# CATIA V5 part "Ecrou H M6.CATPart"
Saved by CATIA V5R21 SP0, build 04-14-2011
Part number: Ecrou H M6
Material "Acier": density 7860 kg/m3, Young's modulus 2e+11 Pa, Poisson ratio 0.266, thermal expansion 1.17e-05 1/K
Bounding box of the stored display mesh (mm): x -4 to 4, y -4.619 to 4.619, z 0 to 3
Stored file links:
  C:\Users\Olivier\Desktop\redaction CATIA (local)\CATIA\DONNEES\Exercice assemblage 1 (chassis et socle)\Assemblage chassis et socle (Product inclus)\Ecrou H M6.CATPart
  C:\Program Files\Dassault Systemes\B21\win_b64\startup\materials\French\Catalog.CATMaterial
  C:\Users\Olivier\Desktop\redaction CATIA (local)\CATIA\DONNEES\Exercice assemblage 1 (chassis et socle)\Assemblage chassis et socle (Product inclus)\CATIA_EnvironmentMap_Satin_512x512.jpg
  C:\Users\Olivier\Desktop\redaction CATIA (local)\pompe à moteur de ventilation refait\Pompe_a_moteur_de_ventilation.CATProduct
  C:\Users\Olivier\Desktop\redaction CATIA (local)\pompe à moteur de ventilation refait\Ecrou a collerette M5.CATPart
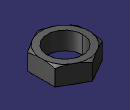
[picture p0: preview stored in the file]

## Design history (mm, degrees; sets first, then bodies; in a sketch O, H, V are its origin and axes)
Body1 (main body), material "Acier"
  Sketch1 on xy-plane, origin (0, 0, 0), H (1, 0, 0), V (0, 1, 0)
    circle A1 centre (0, 0) radius 3
    point P1 (4, -2.3094)
    point P2 (4, 2.3094)
    point P3 (0, 4.6188)
    point P4 (-4, 2.3094)
    point P5 (-4, -2.3094)
    point P6 (0, -4.6188)
    point P7 (4, 0)
    line L1 (4, -2.3094) -> (4, 2.3094)
    line L2 (4, 2.3094) -> (0, 4.6188)
    line L3 (0, 4.6188) -> (-4, 2.3094)
    line L4 (-4, 2.3094) -> (-4, -2.3094)
    line L5 (-4, -2.3094) -> (0, -4.6188)
    line L6 (0, -4.6188) -> (4, -2.3094)
    construction line L7 (0, 0) -> (4, 0)
    construction circle A2 centre (0, 0) radius 4.6188
    construction arc A3 centre (-4, -2.3094) radius 4.6188 from (-4, 2.3094) to (0, -4.6188) cw
    construction arc A4 centre (4, 2.3094) radius 4.6188 from (0, 4.6188) to (4, -2.3094) ccw
    distance L1 L4 = 8
    horizontal: L7 H
    coincidence: A2 P1, A2 P2, A2 P3, A2 P4, A2 P5, A2 P6, A3 O, A4 O
    midpoint: P7 L1
    parallelism: L1 L4
  Pad1: profile Sketch1, direction (0, 0, 1), length 3
  Sketch2 on yz-plane, origin (0, 0, 0), H (0, 1, 0), V (0, 0, 1)
    line L1 (3.8458, 3.1016) -> (4.7183, 2.6279)
    line L2 (4.7183, 2.6279) -> (4.7183, 3.1016)
    line L3 (4.7183, 3.1016) -> (3.8458, 3.1016)
    vertical: L2 V
    horizontal: L3 H
  Groove1: profile Sketch2, axis Sketch2.V, angle 360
